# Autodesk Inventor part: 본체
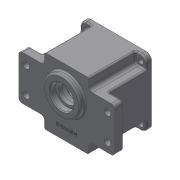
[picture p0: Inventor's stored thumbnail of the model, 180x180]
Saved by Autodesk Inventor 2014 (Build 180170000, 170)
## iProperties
Created: 2014-12
Part Number: 본체
Material: Generic
Document SubType Name: Modeling
Designer: MYHOME
Density: 1 g/cm^3
Appearance: Default
Author: MYHOME
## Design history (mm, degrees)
sketch "스케치2"
  geometry: L1 (-45, -45)-(45, -45); L2 (45, -45)-(45, 45); L3 (45, 45)-(-45, 45); L4 (-45, 45)-(-45, -45); L5 (-45, -45)-(45, 45); L6 (45, -45)-(-45, 45); 1 further point
  constraints: 12 end point, 2 midpoint, 2 parallel, 1 horizontal, 1 perpendicular
  dimensions: "d0" = 90 distance of L2.end L3.end; "d1" = 90 distance of L1.end L2.end
extrude "돌출1" new body sketch "스케치2" distance "d2" = 70; taper "d3" = 0 deg
sketch "스케치3"
  geometry: L1 (-65, -30)-(65, -30); L2 (65, -30)-(65, 30); L3 (65, 30)-(-65, 30); L4 (-65, 30)-(-65, -30); L5 (-65, -30)-(65, 30); L6 (65, -30)-(-65, 30); 1 further point
  constraints: 12 end point, 2 midpoint, 2 parallel, 1 horizontal, 1 perpendicular
  dimensions: "d4" = 130 distance of L2.end L3.end; "d5" = 60 distance of L1.end L2.end
extrude "돌출2" join sketch "스케치3" distance "d6" = 12; taper "d7" = 0 deg
sketch "스케치4"
  geometry: L1 (45, 30)-(45, 45) reference; L2 (45, 45)-(-45, 45) reference; L3 (-45, 45)-(-45, 30) reference; L4 (-45, -30)-(-45, -45) reference; L5 (-45, -45)-(45, -45) reference; L6 (-45, 45)-(-30, 45); L7 (-30, 45)-(-30, 30); L8 (-30, 30)-(-45, 30); L9 (-45, 30)-(-45, 45); L10 (45, 45)-(30, 45); L11 (30, 45)-(30, 30); L12 (30, 30)-(45, 30); L13 (45, 30)-(45, 45); L14 (45, -45)-(30, -45); L15 (30, -45)-(30, -30); L16 (30, -30)-(45, -30); L17 (45, -30)-(45, -45); L18 (-45, -45)-(-30, -45); L19 (-30, -45)-(-30, -30); L20 (-30, -30)-(-45, -30); L21 (-45, -30)-(-45, -45); 1 further point
  constraints: 32 end point, 8 parallel, 4 horizontal, 4 perpendicular
  dimensions: "d8" = 15 distance between parallel lines of L3 L7; "d9" = 15 distance between parallel lines of L2 L8 (= d8); "d10" = 15 distance between parallel lines of L1 L11 (= d8); "d11" = 15 distance between parallel lines of L12 L2 (= d8); "d12" = 15 distance between parallel lines of L17 L15 (= d8); "d13" = 15 distance between parallel lines of L5 L16 (= d8); "d14" = 15 distance between parallel lines of L5 L20 (= d8); "d15" = 15 distance between parallel lines of L19 L4 (= d8)
extrude "돌출3" cut sketch "스케치4" distance "d16" = 63; taper "d17" = 0 deg
fillet "모깎기-8" dims "d18" = 8
fillet "모깎기-5" dims "d19" = 5
sketch "스케치5"
  geometry: L1 (-37, -37)-(37, -37); L2 (37, -37)-(37, 37); L3 (37, 37)-(-37, 37); L4 (-37, 37)-(-37, -37); L5 (-37, -37)-(37, 37); L6 (37, -37)-(-37, 37); 7 further points
  constraints: 12 end point, 5 coincident, 3 midpoint, 2 parallel, 1 horizontal, 1 perpendicular
  dimensions: "d20" = 74 distance of L2.end L3.end; "d21" = 74 distance of L1.end L2.end
hole "구멍1" sketch "스케치5" at (-37, 37), (37, 37), (37, -37), (-37, -37) diameter "d22" = 7; stored, may be unused: countersink angle "d26" = 90 deg, drill point angle "d28" = 118 deg; dims "d23" = 6, "d24" = 4, "d25" = 2, "d27" = 8
sketch "스케치6"
  geometry: L1 (-55, -17.5)-(55, -17.5); L2 (55, -17.5)-(55, 17.5); L3 (55, 17.5)-(-55, 17.5); L4 (-55, 17.5)-(-55, -17.5); L5 (-55, -17.5)-(55, 17.5); L6 (55, -17.5)-(-55, 17.5); 5 further points
  constraints: 12 end point, 4 coincident, 2 midpoint, 2 parallel, 1 horizontal, 1 perpendicular
  dimensions: "d29" = 110 distance of L2.end L3.end; "d30" = 35 distance of L1.end L2.end
hole "구멍2" sketch "스케치6" at (-55, 17.5), (-55, -17.5), (55, -17.5), (55, 17.5) diameter "d31" = 9; stored, may be unused: countersink angle "d35" = 90 deg, drill point angle "d37" = 118 deg; dims "d32" = 6, "d33" = 4, "d34" = 2, "d36" = 8
fillet "모깎기3" dims "d38" = 2
sketch "스케치7"
  geometry: C1 r 25 at (0, 11); 1 further point
  constraints: 1 centre point, 1 vertical alignment
  dimensions: "d39" = 50 diameter of C1; "d40" = 11 distance of point (0, 0) C1.centre
extrude "돌출4" join sketch "스케치7" distance "d41" = 7; taper "d42" = 0 deg
fillet "모깎기4" dims "d43" = 2
sketch "스케치8"
  geometry: C1 r 40 at (0, 0); 1 further point
  constraints: 1 centre point, 1 coincident
  dimensions: "d44" = 40 radius of C1
extrude "돌출5" cut sketch "스케치8" distance "d45" = 9; taper "d46" = 0 deg
sketch "스케치9"
  geometry: C1 r 40 at (0, 0) reference; C2 r 39 at (0, 0)
  constraints: 1 centre point, 1 coincident
  dimensions: "d47" = 78 diameter of C2
extrude "돌출6" cut sketch "스케치9" distance "d48" = 52; taper "d49" = 0 deg
sketch "스케치10" dims "d50" = 70
  geometry: L1 (24.749, 24.749)-(-24.749, -24.749); L2 (-24.749, 24.749)-(24.749, -24.749); L3 (-35, 0)-(35, 0); A1 r 4 centre (24.749, 24.749) between (21.809, 27.462) and (27.462, 21.809); A2 r 4 centre (-24.749, 24.749) between (-27.462, 21.809) and (-21.809, 27.462); A3 r 4 centre (-24.749, -24.749) between (-21.809, -27.462) and (-27.462, -21.809); A4 r 4 centre (24.749, -24.749) between (27.462, -21.809) and (21.809, -27.462); A5 r 3.5 centre (19.238, -29.836) between (21.134, -32.777) and (21.762, -27.412); A6 r 3.5 centre (29.836, -19.238) between (27.412, -21.762) and (32.777, -21.134); A7 r 3.5 centre (29.836, 19.238) between (32.777, 21.134) and (27.412, 21.762); A8 r 3.5 centre (19.238, 29.836) between (21.762, 27.412) and (21.134, 32.777); A9 r 3.5 centre (-19.238, 29.836) between (-21.134, 32.777) and (-21.762, 27.412); A10 r 3.5 centre (-29.836, 19.238) between (-27.412, 21.762) and (-32.777, 21.134); A11 r 3.5 centre (-29.836, -19.238) between (-32.777, -21.134) and (-27.412, -21.762); A12 r 3.5 centre (-19.238, -29.836) between (-21.762, -27.412) and (-21.134, -32.777); 5 further points
  constraints: 32 point on circle, 12 centre point, 8 tangent, 7 equal radius, 6 coincident, 6 end point, 4 midpoint, 1 horizontal, 36 other
  dimensions: "d51" = 45 deg angle of L1 L3; "d52" = 90 deg angle of L1 L2; "d53" = 8 diameter of A1; "d54" = 8 diameter of A2; "d55" = 8 diameter of A3; "d56" = 8 diameter of A4; "d57" = 7 diameter of A12
extrude "돌출7" join sketch "스케치10" distance "d58" = 52; taper "d59" = 0 deg
sketch "스케치11"
  geometry: A1 r 4 centre (24.749, -24.749) between (27.462, -21.809) and (21.809, -27.462) reference; A2 r 4 centre (-24.749, -24.749) between (-21.809, -27.462) and (-27.462, -21.809) reference; A3 r 4 centre (-24.749, 24.749) between (-27.462, 21.809) and (-21.809, 27.462) reference; A4 r 4 centre (24.749, 24.749) between (21.809, 27.462) and (27.462, 21.809) reference; 4 further points
  constraints: 4 coincident
hole "구멍3" sketch "스케치11" at (-24.749, 24.749), (24.749, 24.749), (24.749, -24.749), (-24.749, -24.749) diameter "d60" = 3.459; stored, may be unused: countersink angle "d64" = 90 deg, drill point angle "d66" = 118 deg; dims "d61" = 12, "d62" = 4, "d63" = 2, "d65" = 15
sketch "스케치12"
  geometry: A1 r 39 centre (0, 0) between (32.777, -21.134) and (32.777, 21.134) reference; A2 r 39 centre (0, 0) between (-32.777, 21.134) and (-32.777, -21.134) reference; A3 r 20.5 centre (0, -11) between (-7.402, 8.117) and (7.402, 8.117); A4 r 14 centre (0, 20) between (7.402, 8.117) and (-7.402, 8.117)
  constraints: 4 point on circle, 2 centre point, 2 vertical alignment
  dimensions: "d67" = 41 diameter of A3; "d68" = 28 diameter of A4; "d69" = 11 distance of A1.centre A3.centre; "d70" = 20 distance of A1.centre A4.centre
extrude "돌출8" join sketch "스케치12" distance "d71" = 7; taper "d72" = 0 deg
fillet "모깎기5" dims "d73" = 3
fillet "모깎기6" dims "d74" = 2
sketch "스케치13"
  geometry: C1 r 17.5 at (0, -11); A1 r 20.5 centre (0, -11) between (-11.115, 6.225) and (11.115, 6.225) reference; 1 further point
  constraints: 1 centre point, 1 coincident
  dimensions: "d75" = 35 diameter of C1
extrude "돌출9" cut sketch "스케치13" distance "d76" = 10; taper "d77" = 0 deg
sketch "스케치14"
  geometry: C1 r 17.5 at (0, 0) reference; C2 r 12.5 at (0, 0); 1 further point
  constraints: 1 centre point, 1 coincident
  dimensions: "d78" = 25 diameter of C2
extrude "돌출10" cut sketch "스케치14" distance "d79" = 5; taper "d80" = 0 deg
sketch "스케치15"
  geometry: C1 r 23 at (0, 0) reference; C2 r 16 at (0, 0); 1 further point
  constraints: 1 centre point, 1 coincident
  dimensions: "d81" = 32 diameter of C2
extrude "돌출11" cut sketch "스케치15" distance "d82" = 8; taper "d83" = 0 deg
chamfer "모따기1" distance "d84" = 1; stored, may be unused: second distance "d85" = 2, angle "d86" = 45 deg
fillet "모깎기7" dims "d87" = 0.3
sketch "스케치16"
  geometry: C1 r 11 at (0, 20); A1 r 14 centre (0, 20) between (10.493, 10.732) and (-10.493, 10.732) reference; 1 further point
  constraints: 1 centre point, 1 coincident
  dimensions: "d88" = 22 diameter of C1
extrude "돌출12" cut sketch "스케치16" distance "d89" = 7; taper "d90" = 0 deg
sketch "스케치17"
  geometry: C1 r 11 at (0, 0) reference; C2 r 9.5 at (0, 0); 1 further point
  constraints: 1 centre point, 1 coincident
  dimensions: "d91" = 19 diameter of C2
extrude "돌출13" cut sketch "스케치17" distance "d92" = 1; taper "d93" = 0 deg
fillet "모깎기8" dims "d94" = 2
fillet "모깎기9" dims "d95" = 0.3
fillet "모깎기10" dims "d96" = 2
chamfer "모따기2" distance "d97" = 1; stored, may be unused: second distance "d98" = 2, angle "d99" = 45 deg
sketch "스케치18"
  geometry: L1 (-28, -45)-(28, -45) reference; C1 r 27 at (0, 11) reference; 2 further points
  constraints: 1 vertical alignment, 1 other
  dimensions: "d100" = 15 distance from line of L1 point (0, -30)
feature "엠보싱1" sketch "스케치18" dims "d0" = 90, "d1" = 90, "d101" = 0.5, "d102" = 0
node "솔리드1"
